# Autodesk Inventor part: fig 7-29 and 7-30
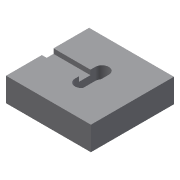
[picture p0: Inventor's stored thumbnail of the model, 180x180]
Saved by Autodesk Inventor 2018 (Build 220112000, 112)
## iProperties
Created: 2004-05
Part Number: fig 7-29 and 7-30
Document SubType Name: Modeling
Designer: CADCIM Technologies
Manufacturer: Standard
Standards Organization: Custom
Density: 1 g/cm^3
Material: Generic
Appearance: Default
Author: CADCIM Technologies
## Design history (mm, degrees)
sketch "Sketch1"
  geometry: L1 (-30.233, -25.517)-(22.302, -25.517); L2 (22.302, -25.517)-(22.302, 25.904); L3 (22.302, 25.904)-(-30.233, 25.904); L4 (-30.233, 25.904)-(-30.233, -25.517)
  constraints: 8 end point, 2 parallel, 1 horizontal, 1 perpendicular
extrude "Extrusion1" new body sketch "Sketch1" distance "d0" = 14.75; taper "d1" = 0 deg
sketch "Sketch2"
  geometry: L1 (1.047, -5.75)-(1.047, 6.846); L2 (-7.35, 6.845)-(-7.35, -5.75); A1 r 4.198 centre (-3.152, 6.846) between (1.047, 6.846) and (-7.35, 6.845); A2 r 4.198 centre (-3.152, -5.75) between (-7.35, -5.75) and (1.047, -5.75)
  constraints: 4 end point, 4 point on circle, 4 tangent, 2 centre point, 1 parallel
extrude "Extrusion2" cut sketch "Sketch2" distance "d2" = 7.5; taper "d3" = 0 deg
sketch "Sketch3"
  geometry: L1 (-7.5, 0)-(-7.5, 12.595) reference; L2 (-7.5, 0)-(0, 0) reference; L3 (-7.5, 2.416)-(-4.537, 2.416); L4 (-4.537, 2.416)-(-4.537, 9.616); L5 (-4.537, 9.616)-(-7.5, 9.616)
  constraints: 6 end point, 2 perpendicular, 2 point on line, 1 parallel
extrude "Extrusion3" cut sketch "Sketch3" extent not by distance; stored distance "d4" = 6.75; taper "d5" = 0 deg
body "Solid1"
